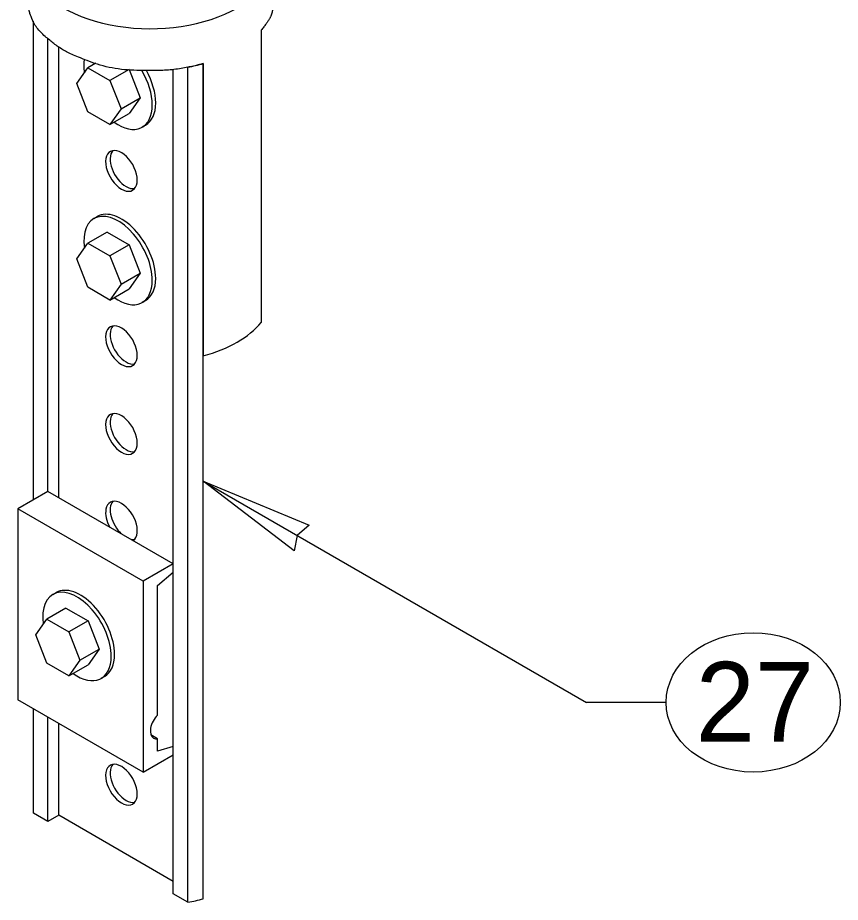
# Model space of a CAD drawing. Extents: x 99862 to 104211, y 98939 to 105076.
# Drawn here: x 100376.2 to 100541.4, y 103735.7 to 103913.4 of the extents above; entities that cross this region are included whole.
import ezdxf

# ---------------------------------------------------------------- set-up
doc = ezdxf.new("R2010")
doc.units = 0
for name, color, linetype in [('Default', 7, 'Continuous'), ('Level 13', 7, 'Continuous'), ('Level 15', 7, 'Continuous'), ('Level 20', 7, 'Continuous'), ('Level 7', 7, 'Continuous')]:
    doc.layers.add(name, color=color, linetype=linetype)

msp = doc.modelspace()

# ---------------------------------------------------------------- linework, layer by layer
at = {"layer": 'Default'}
for p, q in [((100379.35, 103816.56), (100379.35, 103912.68)), ((100425.09, 103910.88), (100425.09, 103852.16)), ((100382.25, 103818.23), (100382.25, 103909.18)), ((100384.43, 103816.97), (100384.43, 103907.54)), ((100407.45, 103737.35), (100407.45, 103903.03)), ((100410.35, 103903.46), (100410.35, 103903.46)), ((100410.35, 103735.68), (100410.35, 103903.46)), ((100413.47, 103904.17), (100413.47, 103845.45)), ((100413.47, 103736.39), (100413.47, 103904.17)), ((100382.25, 103818.23), (100376.19, 103814.73)), ((100407.45, 103803.69), (100382.25, 103818.23)), ((100401.38, 103800.18), (100376.19, 103814.73)), ((100376.19, 103814.73), (100376.19, 103776.35)), ((100407.45, 103803.69), (100401.38, 103800.18)), ((100407.45, 103802.01), (100407.45, 103803.69)), ((100404.28, 103799.33), (100407.45, 103802.01)), ((100401.38, 103800.18), (100401.38, 103761.81)), ((100404.28, 103773.28), (100404.28, 103799.33)), ((100401.38, 103761.81), (100376.19, 103776.35)), ((100379.35, 103753.57), (100379.35, 103774.52)), ((100382.25, 103751.9), (100382.25, 103772.85)), ((100384.43, 103753.15), (100384.43, 103771.59)), ((100404.28, 103768.54), (100402.95, 103769.3)), ((100404.28, 103766.02), (100404.28, 103768.54)), ((100407.41, 103766.98), (100404.28, 103766.02)), ((100401.38, 103761.81), (100407.45, 103765.31)), ((100382.25, 103751.9), (100379.35, 103753.57)), ((100384.43, 103753.15), (100382.25, 103751.9)), ((100407.45, 103739.87), (100384.43, 103753.15)), ((100410.35, 103735.68), (100407.45, 103737.35))]:
    msp.add_line(p, q, dxfattribs=at)
for centre, major_axis, start_param, end_param in [((100402.84, 103917.02), (24.66, 0), 5.021668, 5.15795), ((100397.03, 103882.62), (2.25, -3.89), 0, 3.739442), ((100397.03, 103882.62), (2.25, -3.89), 3.739442, 6.283185), ((100397.94, 103883.15), (-2.25, 3.89), 0.203431, 2.356194), ((100397.94, 103883.15), (-2.25, 3.89), 2.356194, 2.938162), ((100397.03, 103847.39), (2.25, -3.89), 0, 3.739442), ((100397.94, 103847.91), (-2.25, 3.89), 0.203431, 2.356194), ((100402.84, 103858.29), (24.66, 0), 5.15795, 5.837624), ((100397.03, 103847.39), (2.25, -3.89), 3.739442, 6.283185), ((100397.94, 103847.91), (-2.25, 3.89), 2.356194, 2.938162), ((100397.03, 103829.77), (2.25, -3.89), 0, 3.739442), ((100397.94, 103830.3), (-2.25, 3.89), 0.203431, 2.356194), ((100397.03, 103829.77), (2.25, -3.89), 3.739442, 6.283185), ((100397.94, 103830.3), (-2.25, 3.89), 2.356194, 2.938162), ((100397.03, 103812.15), (2.25, -3.89), 0.053055, 3.739442), ((100397.94, 103812.68), (-2.25, 3.89), 0.203431, 2.052802), ((100397.03, 103812.15), (2.25, -3.89), 3.739442, 4.659334), ((100397.94, 103812.68), (-2.25, 3.89), 2.659587, 2.938162), ((100405.01, 103771.33), (-1.54, -2.67), 4.266828, 6.283185), ((100405.01, 103771.33), (-1.54, -2.67), 6.283185, 6.728747), ((100397.03, 103759.3), (2.25, -3.89), 0, 3.739442), ((100397.94, 103759.83), (-2.25, 3.89), 0.203431, 2.356194), ((100397.03, 103759.3), (2.25, -3.89), 3.739442, 6.283185), ((100397.94, 103759.83), (-2.25, 3.89), 2.356194, 2.938162), ((100402.84, 103749.24), (24.66, 0), 5.021668, 5.15795)]:
    msp.add_ellipse(centre, major_axis=major_axis, ratio=0.57735, start_param=start_param, end_param=end_param, dxfattribs=at)
for points, degree in [([(100413.47, 103904.17), (100412.83, 103903.99), (100412.18, 103903.83), (100411.51, 103903.69), (100408.71, 103903.08), (100405.7, 103902.77), (100402.7, 103902.78), (100397.64, 103902.79), (100392.6, 103903.74), (100388.49, 103905.44), (100386.24, 103906.37), (100384.26, 103907.52), (100382.67, 103908.83), (100380.71, 103910.44), (100379.32, 103912.29), (100378.66, 103914.23), (100378.62, 103914.36), (100378.58, 103914.48), (100378.54, 103914.61), (100378.5, 103914.74), (100378.46, 103914.88), (100378.43, 103915.01), (100378.4, 103915.15), (100378.37, 103915.28), (100378.34, 103915.42), (100378.31, 103915.55), (100378.29, 103915.69), (100378.27, 103915.83), (100378.25, 103915.96), (100378.23, 103916.1), (100378.22, 103916.23), (100378.21, 103916.37), (100378.2, 103916.51), (100378.19, 103916.64), (100378.19, 103916.77), (100378.18, 103916.89), (100378.18, 103917.02)], 3), ([(100427.5, 103917.02), (100427.5, 103914.9), (100426.67, 103912.79), (100425.09, 103910.88)], 2)]:
    msp.add_open_spline(points, degree=degree, dxfattribs=at)
at = {"layer": 'Level 13'}
msp.add_ellipse((100402.84, 103925.41), major_axis=(24.66, 0), ratio=0.57735, start_param=3.127072, end_param=6.283185, dxfattribs=at)
at = {"layer": 'Level 15'}
for p in [(100413.47, 103820.28), (100506.44, 103775.84)]:
    msp.add_line(p, (100490.44, 103775.84), dxfattribs=at)
msp.add_lwpolyline([(100413.47, 103820.28), (100434.73, 103811.45), (100432.32, 103809.39), (100431.75, 103806.28)], close=True, dxfattribs=at)
at = {"layer": 'Level 20'}
msp.add_ellipse((100523.94, 103775.84), major_axis=(-17.5, 0), ratio=0.8, dxfattribs=at)
at = {"layer": 'Level 7'}
for p, q in [((100391.89, 103904.26), (100390.29, 103903.34)), ((100398.56, 103903), (100394.72, 103900.78)), ((100396.94, 103895.07), (100400.78, 103897.29)), ((100394.72, 103891.92), (100398.56, 103894.13)), ((100401.89, 103891.81), (100401.21, 103891.42)), ((100391.48, 103873.04), (100392.16, 103873.43)), ((100394.13, 103870.32), (100390.29, 103868.11)), ((100398.56, 103867.76), (100394.72, 103865.55)), ((100396.94, 103859.84), (100400.78, 103862.05)), ((100394.72, 103856.68), (100398.56, 103858.9)), ((100401.89, 103856.58), (100401.21, 103856.18)), ((100383.23, 103797.5), (100383.92, 103797.9)), ((100385.88, 103794.79), (100382.04, 103792.57)), ((100390.31, 103792.23), (100386.47, 103790.01)), ((100388.69, 103784.3), (100392.53, 103786.52)), ((100386.47, 103781.15), (100390.31, 103783.36)), ((100393.65, 103781.04), (100392.96, 103780.65))]:
    msp.add_line(p, q, dxfattribs=at)
for points in [[(100390.29, 103903.34), (100394.72, 103900.78), (100396.94, 103895.07), (100394.72, 103891.92), (100390.29, 103894.47), (100388.07, 103900.19)], [(100390.29, 103868.11), (100394.72, 103865.55), (100396.94, 103859.84), (100394.72, 103856.68), (100390.29, 103859.24), (100388.07, 103864.95)], [(100382.04, 103792.57), (100386.47, 103790.01), (100388.69, 103784.3), (100386.47, 103781.15), (100382.04, 103783.71), (100379.83, 103789.42)]]:
    msp.add_lwpolyline(points, close=True, dxfattribs=at)
for points in [[(100398.56, 103903), (100400.78, 103897.29), (100398.56, 103894.13)], [(100394.13, 103870.32), (100398.56, 103867.76), (100400.78, 103862.05), (100398.56, 103858.9)], [(100385.88, 103794.79), (100390.31, 103792.23), (100392.53, 103786.52), (100390.31, 103783.36)]]:
    msp.add_lwpolyline(points, dxfattribs=at)
for centre, start_param, end_param in [((100396.35, 103899.84), 3.768217, 4.107514), ((100396.35, 103899.84), 0.785398, 1.589831), ((100397.03, 103900.24), 0.785398, 1.539778), ((100396.35, 103899.84), 5.384089, 7.068583), ((100397.03, 103900.24), 6.283176, 7.068583), ((100397.03, 103865.01), 0.785398, 3.141597), ((100396.35, 103864.61), 0.785398, 4.107514), ((100396.35, 103864.61), 5.384089, 7.068583), ((100397.03, 103865.01), 6.283176, 7.068583), ((100388.1, 103789.08), 0.785398, 4.107514), ((100388.78, 103789.47), 0.785398, 3.141597), ((100388.1, 103789.08), 5.384089, 7.068583), ((100388.78, 103789.47), 6.283176, 7.068583)]:
    msp.add_ellipse(centre, major_axis=(4.86, -8.43), ratio=0.57735, start_param=start_param, end_param=end_param, dxfattribs=at)

# ---------------------------------------------------------------- texts
at = {"layer": 'Level 20'}
msp.add_text('27', height=16, dxfattribs=at).set_placement((100512.39, 103767.97))

doc.saveas('drawing.dxf')
